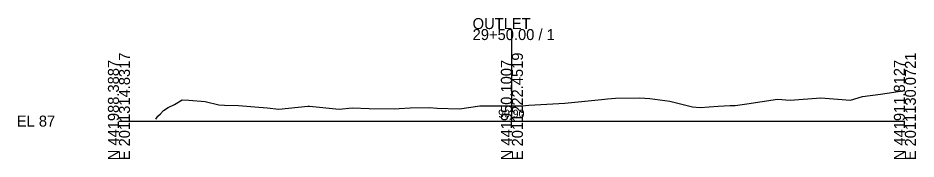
# Model space of a CAD drawing. Extents: x -26 to 1203, y -15 to 9526.
# Drawn here: x 974.3 to 1202.8, y 9490.3 to 9526.3 of the extents above; entities that cross this region are included whole.
import ezdxf

# ---------------------------------------------------------------- set-up
doc = ezdxf.new("R2010")
doc.units = 0
for name, color, linetype in [('Exist Cross Section Cell', 7, 'Continuous'), ('Exist XS Center Line Elevation Label', 7, 'Continuous'), ('Exist XS Ground Line', 7, 'Continuous')]:
    doc.layers.add(name, color=color, linetype=linetype)

msp = doc.modelspace()

# ---------------------------------------------------------------- linework, layer by layer
at = {"layer": 'Exist Cross Section Cell'}
for p, q in [((1100, 9500), (1100, 9523.47)), ((1000, 9500), (1100, 9500)), ((1100, 9500), (1200, 9500))]:
    msp.add_line(p, q, dxfattribs=at)
at = {"layer": 'Exist XS Ground Line'}
msp.add_lwpolyline([(1009.41, 9500.53), (1009.91, 9501.23), (1010.54, 9501.88), (1011.37, 9502.7), (1012.5, 9503.44), (1014.15, 9504.2), (1016.06, 9505.42), (1017.77, 9505.34), (1021.91, 9504.99), (1025.42, 9504.18), (1026.88, 9504.07), (1030.4, 9503.99), (1037.7, 9503.38), (1040.73, 9503.04), (1048.03, 9503.79), (1048.53, 9503.81), (1056.04, 9503), (1059.35, 9503.37), (1063.69, 9503.22), (1070.18, 9503.14), (1071.34, 9503.18), (1074.15, 9503.35), (1078.99, 9503.44), (1081, 9503.33), (1086.65, 9503.11), (1091.83, 9503.88), (1094.3, 9503.88), (1100.26, 9503.9), (1102.65, 9503.86), (1104.35, 9504.05), (1113.48, 9504.57), (1122.83, 9505.53), (1124.3, 9505.66), (1126.38, 9505.83), (1132.57, 9505.94), (1135.13, 9505.74), (1140.22, 9505.04), (1145.95, 9503.64), (1147.87, 9503.48), (1152.5, 9503.78), (1155.52, 9503.98), (1156.78, 9504.01), (1159.81, 9504.4), (1167.6, 9505.62), (1170.83, 9505.32), (1178.62, 9505.97), (1186.14, 9505.31), (1189.25, 9506.25), (1193.79, 9506.88), (1200, 9507.82)], dxfattribs=at)

# ---------------------------------------------------------------- texts
at = {"layer": 'Exist Cross Section Cell'}
for s, p in [('OUTLET', (1090, 9523.47)), ('29+50.00 / 1', (1090, 9520.67)), ('EL 87', (974, 9498.6))]:
    msp.add_text(s, height=2.8, dxfattribs=at).set_placement(p)
for s, p in [('E 2011314.8317', (1002.8, 9490)), ('E 2011222.4519', (1102.8, 9490)), ('E 2011130.0721', (1202.8, 9490)), ('N 441988.3887', (1000, 9490)), ('N 441950.1007', (1100, 9490)), ('N 441911.8127', (1200, 9490))]:
    msp.add_text(s, height=2.8, rotation=90, dxfattribs=at).set_placement(p)
at = {"layer": 'Exist XS Center Line Elevation Label'}
msp.add_text('90.90', height=2, dxfattribs=at).set_placement((1096.5, 9500.9))

doc.saveas('drawing.dxf')
